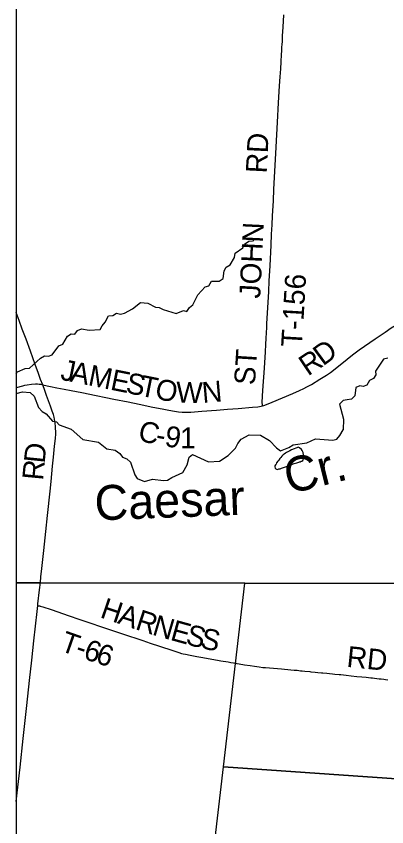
# Model space of a CAD drawing. Extents: x -49 to -8.2, y 9.4 to 23.5.
# Drawn here: x -46.29 to -45.786, y 17.164 to 18.265 of the extents above; entities that cross this region are included whole.
import ezdxf

# ---------------------------------------------------------------- set-up
doc = ezdxf.new("R2010")
doc.units = 0
for name, color, linetype in [('GM_X_Adjacent_County', 7, 'Continuous'), ('GM_X_County_Road', 7, 'Continuous'), ('GM_X_County_Road_Text', 7, 'Continuous'), ('GM_X_Minor_Lake', 7, 'Continuous'), ('GM_X_Minor_River', 7, 'Continuous'), ('GM_X_Minor_River_Text', 7, 'Continuous'), ('GM_X_Township', 7, 'Continuous'), ('GM_X_Township_Road', 7, 'Continuous'), ('GM_X_Township_Road_Text', 7, 'Continuous')]:
    doc.layers.add(name, color=color, linetype=linetype)

msp = doc.modelspace()

# ---------------------------------------------------------------- linework, layer by layer
at = {"layer": 'GM_X_Adjacent_County'}
msp.add_lwpolyline([(-42.0989, 21.0039), (-46.2895, 21.0039), (-46.2895, 15.4273)], dxfattribs=at)
at = {"layer": 'GM_X_County_Road'}
for points in [[(-46.2536, 17.764), (-46.2564, 17.7711), (-46.2594, 17.7793), (-46.2637, 17.7916), (-46.2701, 17.8094), (-46.2762, 17.826), (-46.2813, 17.8397), (-46.2856, 17.8513), (-46.2895, 17.8619)], [(-45.9551, 17.7354), (-45.9533, 17.7359), (-45.9497, 17.7371), (-45.9419, 17.7403), (-45.914, 17.7523), (-45.9051, 17.7561), (-45.8989, 17.759), (-45.8951, 17.761), (-45.8888, 17.7644), (-45.8774, 17.7714), (-45.8684, 17.777), (-45.863, 17.7807), (-45.8563, 17.7858), (-45.8402, 17.7989), (-45.8331, 17.8044), (-45.8238, 17.8112), (-45.8022, 17.8264), (-45.7888, 17.8355), (-45.7803, 17.8411), (-45.775, 17.8443), (-45.7505, 17.8578), (-45.7393, 17.8637), (-45.7388, 17.864)], [(-46.2895, 17.7603), (-46.2892, 17.7604), (-46.2805, 17.7627), (-46.2778, 17.7633), (-46.2745, 17.7639), (-46.269, 17.7647), (-46.2635, 17.7652), (-46.2607, 17.7652), (-46.2585, 17.765), (-46.2563, 17.7646), (-46.2536, 17.764)], [(-46.2559, 17.503), (-46.2546, 17.5146), (-46.252, 17.5387), (-46.2493, 17.5646), (-46.247, 17.5866), (-46.2436, 17.6193), (-46.2423, 17.6326), (-46.2413, 17.6428), (-46.2402, 17.6536), (-46.2389, 17.6657), (-46.2374, 17.6805), (-46.2363, 17.691), (-46.2359, 17.6971), (-46.2359, 17.7005), (-46.2361, 17.7045), (-46.2362, 17.7073), (-46.2368, 17.7116), (-46.2376, 17.7174), (-46.2382, 17.7199), (-46.2391, 17.7235), (-46.2405, 17.7282), (-46.2429, 17.7348), (-46.2482, 17.7494), (-46.2506, 17.7561), (-46.2536, 17.764)], [(-46.2536, 17.764), (-46.2475, 17.7626), (-46.2429, 17.7616)], [(-46.2429, 17.7616), (-46.2342, 17.7599), (-46.2245, 17.7581), (-46.2148, 17.7561), (-46.2004, 17.7533), (-46.181, 17.7493), (-46.1679, 17.7466), (-46.1572, 17.7446), (-46.1377, 17.7407), (-46.1225, 17.7376), (-46.1039, 17.7337), (-46.0915, 17.7311), (-46.0847, 17.7299), (-46.0774, 17.7286), (-46.0691, 17.7274), (-46.0641, 17.7269), (-46.0582, 17.7267), (-46.0523, 17.7269), (-46.0377, 17.7279), (-46.0175, 17.7293), (-46.0027, 17.7306), (-45.9881, 17.7318), (-45.9687, 17.7334), (-45.9615, 17.7341), (-45.9594, 17.7344), (-45.9569, 17.7349), (-45.9551, 17.7354)], [(-46.2602, 17.464), (-46.26, 17.4664), (-46.2579, 17.4853), (-46.2567, 17.4954), (-46.2559, 17.503)], [(-46.2895, 17.1979), (-46.2843, 17.2447), (-46.2802, 17.2833), (-46.2753, 17.3284), (-46.2714, 17.3624), (-46.2683, 17.3898), (-46.2655, 17.4161), (-46.261, 17.4559), (-46.2602, 17.464)]]:
    msp.add_lwpolyline(points, dxfattribs=at)
at = {"layer": 'GM_X_Minor_Lake'}
msp.add_lwpolyline([(-45.9063, 17.6791), (-45.9156, 17.6758), (-45.9179, 17.6742), (-45.9208, 17.6729), (-45.9225, 17.672), (-45.9239, 17.6711), (-45.9256, 17.6698), (-45.9269, 17.6686), (-45.9279, 17.6679), (-45.9291, 17.6668), (-45.9302, 17.6653), (-45.9316, 17.6636), (-45.9331, 17.6617), (-45.9345, 17.66), (-45.936, 17.658), (-45.9368, 17.6563), (-45.9376, 17.655), (-45.9382, 17.654), (-45.9386, 17.6523), (-45.9381, 17.6508), (-45.9371, 17.6497), (-45.9362, 17.6491), (-45.9349, 17.649), (-45.9328, 17.6496), (-45.9311, 17.6499), (-45.9292, 17.6506), (-45.9267, 17.6514), (-45.9238, 17.6523), (-45.9211, 17.6534), (-45.9175, 17.6548), (-45.9146, 17.6561), (-45.912, 17.6568), (-45.9102, 17.6573), (-45.9087, 17.6577), (-45.9072, 17.6584), (-45.9059, 17.6588), (-45.9047, 17.6591), (-45.9038, 17.6595), (-45.9028, 17.66), (-45.9017, 17.6602), (-45.9005, 17.6613), (-45.8997, 17.6623), (-45.8995, 17.6632), (-45.8991, 17.6647), (-45.8993, 17.6664), (-45.8994, 17.6683), (-45.8994, 17.6699), (-45.8998, 17.6708), (-45.8999, 17.672), (-45.9003, 17.6729), (-45.9007, 17.6739), (-45.9012, 17.6748), (-45.902, 17.676), (-45.9048, 17.6783), (-45.9059, 17.6789), (-45.9063, 17.6791)], dxfattribs=at)
at = {"layer": 'GM_X_Minor_River'}
for points in [[(-46.2895, 17.7791), (-46.2877, 17.7817), (-46.2772, 17.7859), (-46.2715, 17.7866), (-46.2565, 17.8002), (-46.2511, 17.8031), (-46.2458, 17.8027), (-46.2409, 17.8047), (-46.2318, 17.8167), (-46.2264, 17.8193), (-46.2198, 17.83), (-46.215, 17.8331), (-46.2099, 17.8329), (-46.2062, 17.8377), (-46.2009, 17.8401), (-46.1907, 17.8381), (-46.1755, 17.839), (-46.1727, 17.8439), (-46.1687, 17.8491), (-46.1642, 17.8578), (-46.1583, 17.8579), (-46.1533, 17.8614), (-46.1479, 17.8598), (-46.1425, 17.8611), (-46.1316, 17.867), (-46.1209, 17.8755), (-46.111, 17.875), (-46.1005, 17.8695), (-46.0956, 17.8691), (-46.0901, 17.866), (-46.0722, 17.8606), (-46.0626, 17.865), (-46.0577, 17.8637), (-46.0544, 17.8688), (-46.0496, 17.8724), (-46.0428, 17.8861), (-46.0328, 17.8971), (-46.028, 17.8984), (-46.0245, 17.9048), (-46.0139, 17.9046), (-46.0087, 17.9084), (-46.007, 17.9186), (-46.0045, 17.9237), (-45.9991, 17.9268), (-45.9931, 17.937), (-45.9922, 17.9425), (-45.9817, 17.9499), (-45.9794, 17.9548), (-45.9738, 17.9589), (-45.9687, 17.9594), (-45.9671, 17.9599)], [(-45.7851, 17.8002), (-45.7908, 17.7986), (-45.8015, 17.7824), (-45.8014, 17.7773), (-45.8045, 17.7724), (-45.8098, 17.7696), (-45.8135, 17.7634), (-45.8183, 17.7616), (-45.8232, 17.7626), (-45.8282, 17.7602), (-45.8299, 17.7491), (-45.8345, 17.7442), (-45.8402, 17.7437), (-45.8457, 17.7425), (-45.8505, 17.7374), (-45.8452, 17.7172), (-45.8455, 17.7029)], [(-46.2895, 17.752), (-46.2809, 17.7544), (-46.2706, 17.7535), (-46.2652, 17.7485), (-46.2594, 17.7329), (-46.2544, 17.7277), (-46.2489, 17.7247), (-46.2403, 17.7145), (-46.235, 17.7135), (-46.2313, 17.7095)], [(-46.2313, 17.7095), (-46.215, 17.7037), (-46.1992, 17.6895), (-46.1776, 17.6862), (-46.1665, 17.6771), (-46.155, 17.675), (-46.1488, 17.6704), (-46.1454, 17.6654), (-46.1394, 17.6633), (-46.1343, 17.659), (-46.1286, 17.6415), (-46.1253, 17.6367), (-46.1155, 17.6326), (-46.1044, 17.6359), (-46.0897, 17.6338), (-46.0843, 17.6345), (-46.0784, 17.6378), (-46.0632, 17.6446), (-46.0572, 17.6552), (-46.0548, 17.6654), (-46.05, 17.6691), (-46.0283, 17.6595), (-46.0137, 17.6603), (-46.0016, 17.6679), (-45.9917, 17.6777), (-45.9887, 17.6844), (-45.9841, 17.6899), (-45.9732, 17.696), (-45.9577, 17.6956), (-45.9458, 17.6884), (-45.9361, 17.6783), (-45.9306, 17.6744), (-45.9194, 17.6786), (-45.9136, 17.6825), (-45.8948, 17.6849), (-45.8832, 17.6903), (-45.8597, 17.6887), (-45.8542, 17.6901), (-45.85, 17.695), (-45.8455, 17.7029)]]:
    msp.add_lwpolyline(points, dxfattribs=at)
at = {"layer": 'GM_X_Township'}
for p, q in [((-46.2895, 19.726), (-46.2895, 17.4947)), ((-46.2895, 17.4947), (-46.2895, 15.4273))]:
    msp.add_line(p, q, dxfattribs=at)
for points in [[(-46.2895, 15.4273), (-46.2741, 15.4259), (-46.1692, 15.4155), (-46.1279, 16.0295), (-46.0985, 16.4665), (-46.0401, 16.9697), (-46.0081, 17.2452), (-45.9918, 17.3853), (-45.9792, 17.4944), (-46.2561, 17.4947), (-46.2895, 17.4947)], [(-46.2895, 17.4947), (-46.2561, 17.4947), (-45.9792, 17.4944), (-45.7318, 17.4945)], [(-45.7538, 17.2272), (-46.0081, 17.2452), (-45.9918, 17.3853), (-45.9792, 17.4944), (-45.7318, 17.4945)], [(-43.7172, 15.1832), (-43.8792, 15.1984), (-44.0636, 15.2153), (-44.1657, 15.2246), (-44.5294, 15.2578), (-44.7618, 15.2786), (-45.515, 15.3548), (-45.7812, 15.377), (-46.1692, 15.4155), (-46.1279, 16.0295), (-46.0985, 16.4665), (-46.0401, 16.9697), (-46.0081, 17.2452), (-45.7538, 17.2272), (-45.2676, 17.1929), (-44.9079, 17.1675), (-44.9078, 17.1687), (-44.8862, 17.4401), (-44.8857, 17.4474), (-44.3512, 17.4033), (-44.12, 17.3857), (-43.5372, 17.3414)]]:
    msp.add_lwpolyline(points, dxfattribs=at)
at = {"layer": 'GM_X_Township_Road'}
for points in [[(-45.9551, 17.7354), (-45.9552, 17.7357), (-45.9553, 17.7373), (-45.9555, 17.7395), (-45.9554, 17.7401), (-45.9545, 17.7562), (-45.9526, 17.7865), (-45.9512, 17.8086), (-45.9507, 17.8185), (-45.9502, 17.8271), (-45.9494, 17.8416), (-45.9491, 17.8467), (-45.9467, 17.8905), (-45.9459, 17.9053), (-45.9449, 17.9255), (-45.9434, 17.9534), (-45.9427, 17.9686), (-45.942, 17.981), (-45.9414, 17.9934), (-45.9404, 18.0139), (-45.9396, 18.0297), (-45.938, 18.0617), (-45.9368, 18.0868), (-45.9349, 18.1206), (-45.9334, 18.1467), (-45.9319, 18.1699), (-45.9311, 18.1823), (-45.9304, 18.1932), (-45.9298, 18.2028), (-45.9297, 18.2056), (-45.9295, 18.2093), (-45.9293, 18.2124), (-45.929, 18.2176), (-45.9288, 18.2207), (-45.9287, 18.2223), (-45.9284, 18.2266), (-45.9282, 18.2297), (-45.928, 18.2328), (-45.9278, 18.2378), (-45.9275, 18.2437), (-45.9272, 18.2495), (-45.9262, 18.2663)], [(-46.2602, 17.464), (-46.2595, 17.4639), (-46.2583, 17.4637), (-46.2574, 17.4636), (-46.2568, 17.4634), (-46.2534, 17.4623), (-46.2422, 17.4586), (-46.2178, 17.4503), (-46.2043, 17.4457), (-46.1937, 17.442), (-46.1698, 17.434), (-46.1451, 17.4256), (-46.1177, 17.4164), (-46.1077, 17.4131), (-46.0951, 17.4088), (-46.0771, 17.4028), (-46.0688, 17.4001), (-46.0653, 17.3991), (-46.0628, 17.3985), (-46.0598, 17.3978), (-46.0534, 17.3965), (-46.0443, 17.3948), (-46.0363, 17.3934), (-46.0238, 17.3912), (-46.0164, 17.3899), (-46.014, 17.3895), (-46.0115, 17.3891), (-46.0085, 17.3885), (-46.0048, 17.3879), (-46.0018, 17.3874), (-45.9981, 17.3868), (-45.9944, 17.3862), (-45.9907, 17.3856), (-45.9899, 17.3854)], [(-45.9899, 17.3854), (-45.9868, 17.3849), (-45.9797, 17.3837), (-45.9721, 17.3825), (-45.9662, 17.3815), (-45.9595, 17.3806), (-45.9549, 17.3801), (-45.9509, 17.3797), (-45.9295, 17.378), (-45.9165, 17.3768), (-45.9122, 17.3764), (-45.9082, 17.3761), (-45.9057, 17.3758), (-45.9036, 17.3756), (-45.9011, 17.3754), (-45.8977, 17.375), (-45.8909, 17.3744), (-45.8894, 17.3742), (-45.8838, 17.3737), (-45.8801, 17.3733), (-45.8752, 17.3728), (-45.8734, 17.3726), (-45.8676, 17.3721), (-45.8642, 17.3718), (-45.8602, 17.3714), (-45.8571, 17.371), (-45.8512, 17.3704), (-45.849, 17.3702), (-45.8416, 17.3695), (-45.8348, 17.3687), (-45.8271, 17.3679), (-45.8203, 17.3672), (-45.8145, 17.3666), (-45.808, 17.3659), (-45.8058, 17.3657), (-45.8031, 17.3653), (-45.8, 17.365), (-45.7966, 17.3646), (-45.7938, 17.3643), (-45.7904, 17.3639), (-45.788, 17.3636), (-45.7849, 17.3632)]]:
    msp.add_lwpolyline(points, dxfattribs=at)

# ---------------------------------------------------------------- texts
at = {"layer": 'GM_X_County_Road_Text'}
for s, rotation, p in [('D', 36.3468, (-45.873, 17.7887)), ('R', 33.9055, (-45.8934, 17.775)), ('J', 348.6151, (-46.2307, 17.7711)), ('A', 348.6143, (-46.2176, 17.7685)), ('M', 348.6172, (-46.1931, 17.7636)), ('E', 348.6153, (-46.1629, 17.7575)), ('S', 348.6125, (-46.1421, 17.7533)), ('T', 348.6164, (-46.1233, 17.7495)), ('O', 348.6464, (-46.1024, 17.7453)), ('W', 358.6137, (-46.0726, 17.7398)), ('N', 5.0516, (-46.0362, 17.7391)), ('C', 347.0931, (-46.1255, 17.6884)), ('9', 351.3649, (-46.089, 17.6806)), ('1', 0.1856, (-46.067, 17.6776)), ('-', 349.406, (-46.1015, 17.6829)), ('D', 84.1248, (-46.251, 17.6565)), ('R', 84.5865, (-46.2532, 17.6334))]:
    msp.add_text(s, height=0.0284, rotation=rotation, dxfattribs=at).set_placement(p)
at = {"layer": 'GM_X_Minor_River_Text'}
for s, rotation, p in [('Cr.', 14.0537, (-45.9191, 17.6152)), ('Caesar', 2.2419, (-46.1823, 17.5796))]:
    msp.add_text(s, height=0.04735, rotation=rotation, dxfattribs=at).set_placement(p)
at = {"layer": 'GM_X_Township_Road_Text'}
for s, height, rotation, p in [('RD', 0.02841, 87.0388, (-45.9495, 18.0507)), ('JOHN', 0.02841, 87.1755, (-45.9583, 17.8807)), ('T-156', 0.02841, 86.6343, (-45.9016, 17.8148)), ('ST', 0.02841, 86.4601, (-45.9654, 17.7629)), ('H', 0.0284, 341.3727, (-46.1769, 17.4483)), ('A', 0.0284, 341.3727, (-46.1532, 17.4403)), ('R', 0.0284, 342.0225, (-46.1292, 17.4322)), ('N', 0.0284, 343.71, (-46.1061, 17.4247)), ('E', 0.0284, 344.6201, (-46.0816, 17.4176)), ('T', 0.0284, 340.6489, (-46.2314, 17.4031)), ('S', 0.0284, 345.0474, (-46.0609, 17.4119)), ('S', 0.0284, 348.2526, (-46.0407, 17.4065)), ('6', 0.0284, 341.6483, (-46.1997, 17.3922)), ('6', 0.0284, 341.6906, (-46.1831, 17.3867)), ('RD', 0.02841, 354.0861, (-45.8417, 17.3809)), ('-', 0.0284, 341.4845, (-46.2109, 17.3959))]:
    msp.add_text(s, height=height, rotation=rotation, dxfattribs=at).set_placement(p)

doc.saveas('drawing.dxf')
